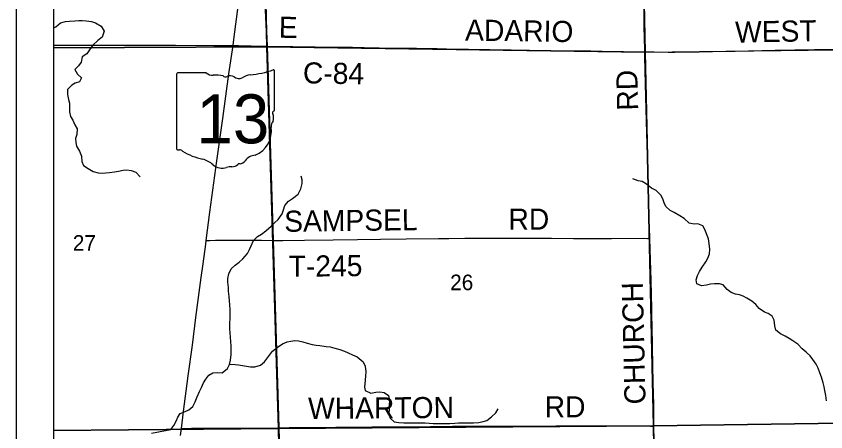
# Model space of a CAD drawing. Extents: x 0 to 70.2, y 0 to 31.4.
# Drawn here: x 2 to 4.18, y 19.306 to 20.424 of the extents above; entities that cross this region are included whole.
import ezdxf

# ---------------------------------------------------------------- set-up
doc = ezdxf.new("R2010")
doc.units = 0
for name, color, linetype in [('GM_X_County_Road', 7, 'Continuous'), ('GM_X_County_Road_Text', 7, 'Continuous'), ('GM_X_Minor_River', 7, 'Continuous'), ('GM_X_Section', 7, 'Continuous'), ('GM_X_Section_Text', 7, 'Continuous'), ('GM_X_State_Location', 7, 'Continuous'), ('GM_X_State_Route', 7, 'Continuous'), ('GM_X_State_Shield', 7, 'Continuous'), ('GM_X_Township_Road', 7, 'Continuous'), ('GM_X_Township_Road_Text', 7, 'Continuous'), ('SH_Cut_Line', 7, 'Continuous'), ('SH_Data', 7, 'Continuous')]:
    doc.layers.add(name, color=color, linetype=linetype)

msp = doc.modelspace()

# ---------------------------------------------------------------- linework, layer by layer
at = {"layer": 'GM_X_County_Road'}
for points in [[(2.1, 20.3462), (2.2177, 20.3466), (2.3669, 20.3464), (2.4291, 20.3461), (2.5317, 20.3455), (2.5752, 20.3451), (2.5837, 20.3451)], [(2.5837, 20.3451), (2.5985, 20.3451), (2.6669, 20.3439), (2.676, 20.3438), (2.677, 20.3438)], [(2.677, 20.3438), (2.7445, 20.3428), (2.865, 20.3413), (2.8749, 20.3409), (2.9056, 20.3408), (2.9369, 20.3404), (2.9774, 20.3395), (3.055, 20.3385), (3.062, 20.3381), (3.0778, 20.338), (3.1149, 20.3372), (3.1337, 20.337), (3.1583, 20.3367), (3.2173, 20.3356), (3.3323, 20.334), (3.382, 20.333), (3.497, 20.3313), (3.5468, 20.3307), (3.5778, 20.3301), (3.6924, 20.3283)], [(3.6924, 20.3283), (3.7175, 20.3279), (3.7548, 20.3276), (3.7734, 20.3275), (3.8387, 20.3284), (3.9101, 20.3298), (3.9352, 20.3303), (4.0435, 20.3325), (4.1495, 20.3344), (4.209, 20.3357), (4.3109, 20.3376), (4.3888, 20.3388), (4.4136, 20.3397), (4.4478, 20.3401), (4.4571, 20.3406), (4.5037, 20.3416), (4.5658, 20.3429), (4.6186, 20.3442), (4.6559, 20.3455), (4.7179, 20.3465)]]:
    msp.add_lwpolyline(points, dxfattribs=at)
at = {"layer": 'GM_X_Minor_River'}
for points in [[(2.1, 20.3931), (2.1071, 20.3958), (2.1197, 20.4059), (2.1331, 20.4099), (2.1437, 20.411), (2.1582, 20.4115), (2.1684, 20.4122), (2.1779, 20.4125), (2.1881, 20.4116), (2.2025, 20.4095), (2.2135, 20.4067), (2.2286, 20.3971), (2.2372, 20.3837), (2.2313, 20.3682), (2.2202, 20.3585), (2.206, 20.3465), (2.1971, 20.334), (2.1906, 20.3231), (2.1772, 20.3145), (2.1747, 20.3001), (2.1674, 20.2903), (2.1578, 20.281), (2.1649, 20.2684), (2.1762, 20.2587), (2.1707, 20.2478), (2.1589, 20.2441), (2.1494, 20.2389), (2.1379, 20.2273), (2.1381, 20.2136), (2.1406, 20.2003), (2.1435, 20.1904), (2.1438, 20.1767), (2.1436, 20.1672), (2.1462, 20.1547), (2.1525, 20.144), (2.1577, 20.1318), (2.1644, 20.1207), (2.1635, 20.1063), (2.1595, 20.0953), (2.1602, 20.0847), (2.1624, 20.0748)], [(2.1624, 20.0748), (2.1702, 20.061), (2.1757, 20.0477), (2.1763, 20.0332), (2.1815, 20.0229), (2.1936, 20.0148), (2.2075, 20.0067), (2.2208, 20.0023), (2.2318, 20.0018), (2.2417, 20.0025), (2.2515, 20.0039), (2.2645, 20.0056), (2.2751, 20.0074), (2.2877, 20.0096), (2.2975, 20.0106), (2.3097, 20.0093), (2.3222, 20.0042), (2.3338, 19.9916)], [(2.364, 19.3021), (2.4024, 19.3094), (2.4164, 19.3124), (2.4248, 19.3226), (2.4309, 19.3347), (2.4352, 19.3453), (2.4417, 19.3555), (2.455, 19.3608), (2.4652, 19.3649), (2.4751, 19.3736), (2.482, 19.3864), (2.487, 19.4001), (2.4939, 19.4148), (2.4985, 19.4255), (2.5039, 19.438), (2.5104, 19.4478), (2.5188, 19.458), (2.5295, 19.4648), (2.5416, 19.4655), (2.5545, 19.4647), (2.5686, 19.476), (2.5747, 19.4866), (2.5771, 19.4991), (2.5783, 19.5135), (2.5784, 19.5367), (2.5777, 19.5488), (2.5766, 19.5598), (2.5759, 19.572), (2.5756, 19.5826), (2.5752, 19.5963), (2.5757, 19.6126), (2.5758, 19.635), (2.5751, 19.6475), (2.5744, 19.6585), (2.5737, 19.6703), (2.5719, 19.684), (2.5715, 19.6946), (2.5701, 19.7083), (2.5701, 19.7181), (2.5725, 19.7306), (2.5786, 19.7447), (2.5897, 19.7545), (2.5999, 19.7624), (2.6102, 19.7711), (2.6228, 19.7854), (2.6282, 19.7964), (2.6324, 19.8066), (2.6389, 19.8207), (2.6492, 19.8312), (2.6603, 19.838), (2.6717, 19.8467), (2.6862, 19.8591), (2.6957, 19.8686), (2.7056, 19.8773), (2.7159, 19.8924), (2.7194, 19.9034), (2.7232, 19.9144), (2.7328, 19.9265), (2.7442, 19.9336), (2.7587, 19.9457), (2.7667, 19.9597), (2.7702, 19.9737), (2.7695, 19.984), (2.7669, 19.9942)], [(3.903, 19.7018), (3.8935, 19.7045), (3.8799, 19.7042), (3.8696, 19.7031), (3.8582, 19.7001), (3.8453, 19.6983), (3.8321, 19.704), (3.8306, 19.7146), (3.8341, 19.7268), (3.8394, 19.737), (3.8471, 19.7491), (3.8566, 19.7631), (3.8616, 19.7729), (3.8662, 19.7847), (3.867, 19.7976), (3.8656, 19.8128), (3.8634, 19.8249), (3.8585, 19.839), (3.8548, 19.8485), (3.8484, 19.8599), (3.8351, 19.8657), (3.8252, 19.865), (3.8116, 19.8673), (3.7984, 19.8799), (3.7863, 19.8872), (3.7711, 19.8964), (3.7609, 19.9013), (3.7492, 19.912), (3.7443, 19.9219), (3.7406, 19.9326), (3.7357, 19.9428), (3.7229, 19.955), (3.71, 19.9612), (3.6968, 19.9723), (3.685, 19.9795), (3.674, 19.9811), (3.66, 19.9865)], [(4.1815, 19.3892), (4.1793, 19.4032), (4.1767, 19.4173), (4.1749, 19.4268), (4.1727, 19.4378), (4.1682, 19.4526), (4.1637, 19.4648), (4.1588, 19.477), (4.1535, 19.4876), (4.1449, 19.5006), (4.1377, 19.5101), (4.1268, 19.52), (4.1162, 19.5295), (4.1041, 19.5414), (4.0905, 19.5505), (4.0806, 19.5571), (4.07, 19.5632), (4.0572, 19.5697), (4.0451, 19.5792), (4.0425, 19.591), (4.0407, 19.6062), (4.035, 19.6172), (4.0248, 19.6245), (4.0146, 19.6276), (4.0006, 19.6379), (3.9915, 19.6482), (3.9802, 19.657), (3.967, 19.6658), (3.9567, 19.6711), (3.9469, 19.6742), (3.9363, 19.6766), (3.9245, 19.6808), (3.9143, 19.6888), (3.903, 19.7018)], [(2.575, 19.488), (2.5891, 19.4869), (2.5986, 19.4861), (2.6092, 19.4841), (2.6202, 19.4822), (2.6305, 19.481), (2.6422, 19.4809), (2.6574, 19.485), (2.6681, 19.4945), (2.6795, 19.5088), (2.6899, 19.5228), (2.7024, 19.5326), (2.7165, 19.5424), (2.7294, 19.5477), (2.7393, 19.5499), (2.7499, 19.5514), (2.7598, 19.551), (2.7716, 19.5482), (2.7837, 19.5444), (2.7966, 19.5409), (2.8072, 19.5393), (2.8178, 19.5382), (2.8345, 19.5358), (2.8451, 19.5346), (2.8576, 19.5307), (2.8713, 19.5276), (2.8837, 19.523), (2.894, 19.5184), (2.9057, 19.5131), (2.9178, 19.5077), (2.9337, 19.4943), (2.9393, 19.4829), (2.9412, 19.467), (2.9407, 19.4567), (2.9395, 19.4453), (2.9379, 19.4264), (2.9398, 19.4169), (2.9545, 19.4103), (2.9682, 19.4129), (2.9788, 19.4133), (2.9906, 19.4113), (3.0023, 19.4033), (3.0049, 19.3911), (3.0041, 19.3756), (3.0037, 19.3657), (3.0036, 19.3554), (3.0066, 19.3425), (3.0172, 19.333), (3.0297, 19.3306), (3.0437, 19.3302), (3.0532, 19.3305), (3.0729, 19.3304), (3.0885, 19.33), (3.1006, 19.3299), (3.1116, 19.3291), (3.123, 19.3283), (3.1332, 19.3279), (3.1511, 19.3285), (3.167, 19.3285), (3.1807, 19.3295), (3.1905, 19.3299), (3.2034, 19.3302), (3.216, 19.3301), (3.2308, 19.3304), (3.2452, 19.3311), (3.2573, 19.3333), (3.2668, 19.3367), (3.2798, 19.3461), (3.2916, 19.3571), (3.2973, 19.3673)]]:
    msp.add_lwpolyline(points, dxfattribs=at)
at = {"layer": 'GM_X_Section'}
for points in [[(3.6935, 20.3278), (3.7154, 19.3219), (2.7066, 19.3148), (2.6748, 20.3422)], [(4.716, 20.3402), (4.7288, 19.3363), (3.7154, 19.3219), (3.6935, 20.3278)], [(3.7154, 19.3219), (4.7288, 19.3363), (4.7368, 18.3286), (4.7171, 18.3286), (3.7317, 18.3233)], [(2.7066, 19.3148), (3.7154, 19.3219), (3.7317, 18.3233), (3.715, 18.323), (2.7267, 18.3203)]]:
    msp.add_lwpolyline(points, close=True, dxfattribs=at)
at = {"layer": 'GM_X_Section_Text'}
for points in [[(2.1, 20.9), (2.1, 18.3126), (2.2164, 18.3137), (2.2784, 18.3145), (2.3277, 18.3152), (2.3343, 18.3153), (2.3412, 18.3156), (2.3574, 18.3156), (2.4158, 18.3166), (2.4655, 18.3166), (2.5245, 18.3166), (2.5804, 18.317), (2.6618, 18.318), (2.7031, 18.3186), (2.7265, 18.319), (2.7342, 18.3192), (2.7194, 18.8581), (2.7067, 19.3173), (2.6915, 19.8217), (2.6758, 20.3443), (2.6527, 20.8458)], [(2.6527, 20.8458), (2.6758, 20.3443), (2.6915, 19.8217), (2.7067, 19.3173), (2.7194, 18.8581)]]:
    msp.add_lwpolyline(points, dxfattribs=at)
at = {"layer": 'GM_X_State_Route'}
for points in [[(2.6618, 20.9), (2.1, 20.9), (2.1, 20.3392), (2.6748, 20.3422)], [(3.6817, 20.9), (2.6618, 20.9), (2.6748, 20.3422), (3.6935, 20.3278)], [(4.7047, 20.9), (3.6817, 20.9), (3.6935, 20.3278), (4.716, 20.3402)], [(2.1, 20.3392), (2.1, 19.3098), (2.7066, 19.3148), (2.6748, 20.3422)], [(2.1, 19.3098), (2.1, 18.3121), (2.6994, 18.3199), (2.7267, 18.3203), (2.7066, 19.3148)]]:
    msp.add_lwpolyline(points, close=True, dxfattribs=at)
msp.add_lwpolyline([(2.4422, 19.2959), (2.4446, 19.3145), (2.4507, 19.3606), (2.4634, 19.4561), (2.4743, 19.5393), (2.484, 19.6132), (2.4982, 19.7211), (2.5032, 19.758), (2.5101, 19.8104), (2.5114, 19.8207), (2.5212, 19.8967), (2.5405, 20.0353), (2.5562, 20.1492), (2.5728, 20.2693), (2.5837, 20.3451), (2.5861, 20.3616), (2.5988, 20.4571)], dxfattribs=at)
at = {"layer": 'GM_X_State_Shield'}
for p, q in [((2.5115, 20.2715), (2.4343, 20.2715)), ((2.6953, 20.1718), (2.6953, 20.2765)), ((2.4317, 20.2681), (2.4317, 20.068)), ((2.6953, 20.1718), (2.6953, 20.1718))]:
    msp.add_line(p, q, dxfattribs=at)
for centre, radius, start, end in [((2.4347, 20.2685), 0.00305, 98.1301, 188.1301), ((2.5299, 20.2948), 0.0296, 231.6195, 271.1119), ((2.6014, 20.5444), 0.2796, 275.8445, 288.9065), ((2.6924, 20.2769), 0.00294, 351.8621, 97.738), ((2.5397, 20.1592), 0.1064, 80.4867, 94.9883), ((2.5638, 20.2695), 0.00855, 219.7921, 297.1024), ((2.5764, 20.2464), 0.0178, 54.4667, 119.1411), ((2.5993, 20.2781), 0.0214, 233.8562, 294.8282), ((2.6371, 20.2104), 0.0563, 97.3462, 120.7689), ((2.6947, 20.1641), 0.00454, 107.944, 210.337), ((2.6658, 20.1509), 0.0273, 340.033, 23.6496), ((2.6922, 20.1714), 0.00314, 289.6038, 7.7341), ((2.7059, 20.128), 0.0198, 136.8065, 186.9296), ((2.6171, 20.1147), 0.0699, 292.3089, 8.9858), ((2.4347, 20.0675), 0.00308, 171.9584, 258.3066), ((2.4352, 20.088), 0.0235, 267.339, 280.6039), ((2.44, 20.0564), 0.00848, 29.7484, 93.2717), ((2.5471, 20.2362), 0.2019, 240.4129, 257.1985), ((2.4869, 19.9781), 0.0632, 47.1842, 75.836), ((2.598, 20.0486), 0.0226, 282.8732, 323.2771), ((2.6466, 20.0118), 0.0383, 94.4031, 142.5768), ((2.5552, 20.0554), 0.0401, 230.7004, 286.2918), ((2.5784, 19.9862), 0.0329, 85.6951, 111.2099), ((2.5813, 20.0404), 0.0214, 268.777, 315.5493), ((2.6006, 20.0211), 0.00601, 65.7517, 132.6484)]:
    msp.add_arc(centre, radius, start, end, dxfattribs=at)
at = {"layer": 'GM_X_Township_Road'}
for points in [[(3.6924, 20.3283), (3.6925, 20.3342), (3.691, 20.3963), (3.6903, 20.4678), (3.6888, 20.5517), (3.6869, 20.6605), (3.6849, 20.7724), (3.6837, 20.8252), (3.6835, 20.833)], [(3.7062, 19.8263), (3.7059, 19.8307), (3.7044, 19.871), (3.702, 19.9425), (3.701, 19.9922), (3.6998, 20.0481), (3.6972, 20.1414), (3.6955, 20.2066), (3.6934, 20.2781), (3.6925, 20.3154), (3.6924, 20.3283)], [(2.5114, 19.8207), (2.5209, 19.8209), (2.5365, 19.8212), (2.6608, 19.8213), (2.6917, 19.8211)], [(2.6917, 19.8211), (2.7105, 19.8211), (2.7175, 19.8211)], [(2.7175, 19.8211), (2.7758, 19.8215), (2.8536, 19.8224), (2.9189, 19.8233), (2.9811, 19.824), (3.0495, 19.8249), (3.1366, 19.8262), (3.1645, 19.8263), (3.2081, 19.8268), (3.2982, 19.8271), (3.4413, 19.8265), (3.5004, 19.8262), (3.603, 19.8261), (3.6901, 19.8265), (3.6994, 19.8264), (3.7062, 19.8263)], [(3.7168, 19.3213), (3.7165, 19.3786), (3.7151, 19.4376), (3.713, 19.5339), (3.7117, 19.592), (3.7113, 19.6167), (3.7111, 19.632), (3.7112, 19.638), (3.7092, 19.7126), (3.7081, 19.7685), (3.7062, 19.8263)], [(2.4446, 19.3145), (2.4533, 19.3148), (2.4719, 19.3154), (2.5061, 19.3153), (2.5682, 19.3156), (2.6335, 19.3159), (2.7069, 19.3168)], [(2.7069, 19.3168), (2.7236, 19.3169), (2.7346, 19.3171)], [(2.7346, 19.3171), (2.8013, 19.3179), (2.8604, 19.3181), (2.9571, 19.3194), (3.0562, 19.3196), (3.1744, 19.3207), (3.1876, 19.3207), (3.1991, 19.3207), (3.2364, 19.3208), (3.2829, 19.3207), (3.2947, 19.3209), (3.3128, 19.3209), (3.3329, 19.3211), (3.3629, 19.3212), (3.4529, 19.3218), (3.5182, 19.322), (3.6428, 19.3218), (3.7075, 19.3212), (3.7168, 19.3213)], [(3.7259, 18.9166), (3.7255, 18.9286), (3.7249, 18.9667), (3.7245, 18.984), (3.7235, 19.015), (3.7223, 19.0616), (3.7213, 19.1113), (3.7205, 19.1486), (3.7192, 19.2014), (3.7168, 19.3213)]]:
    msp.add_lwpolyline(points, dxfattribs=at)
at = {"layer": 'SH_Cut_Line'}
msp.add_lwpolyline([(6.7786, 18.1369), (6.7742, 18.3058), (6.7461, 18.306), (6.749, 19.3206), (6.7395, 20.3365), (6.7343, 20.9), (2.1, 20.9), (2.1, 14.1)], dxfattribs=at)
at = {"layer": 'SH_Data'}
for p, q in [((2, 21), (2, 14)), ((2.1, 20.9), (2.1, 14.1))]:
    msp.add_line(p, q, dxfattribs=at)

# ---------------------------------------------------------------- texts
at = {"layer": 'GM_X_County_Road_Text'}
for s, height, rotation, p in [('E', 0.0568, 358.8773, (2.7066, 20.3663)), ('ADARIO', 0.05682, 359.1164, (3.2083, 20.3588)), ('WEST', 0.05682, 1.0055, (3.9359, 20.353)), ('C-84', 0.05682, 359.1295, (2.7717, 20.2435))]:
    msp.add_text(s, height=height, rotation=rotation, dxfattribs=at).set_placement(p)
at = {"layer": 'GM_X_Section_Text'}
for s, p in [('27', (2.1524, 19.7932)), ('26', (3.1683, 19.687))]:
    msp.add_text(s, height=0.04186, rotation=0, dxfattribs=at).set_placement(p)
at = {"layer": 'GM_X_State_Location'}
msp.add_text('13', height=0.000189, rotation=0, dxfattribs=at).set_placement((2.5128, 20.1409))
for s in ['s', 'r']:
    msp.add_text(s, height=0.000189, dxfattribs=at).set_placement((2.5605, 20.1547))
at = {"layer": 'GM_X_State_Shield'}
msp.add_text('13', height=0.13184, dxfattribs=at).set_placement((2.4853, 20.0821))
at = {"layer": 'GM_X_Township_Road_Text'}
for s, rotation, p in [('RD', 91.4806, (3.6747, 20.1709)), ('SAMPSEL', 0.7605, (2.7219, 19.8438)), ('RD', 0, (3.3253, 19.8497)), ('T-245', 0.5599, (2.7338, 19.7229)), ('CHURCH', 91.3134, (3.6946, 19.3802)), ('WHARTON', 0.4025, (2.7861, 19.3405)), ('RD', 0, (3.4228, 19.3447))]:
    msp.add_text(s, height=0.05682, rotation=rotation, dxfattribs=at).set_placement(p)

doc.saveas('drawing.dxf')
